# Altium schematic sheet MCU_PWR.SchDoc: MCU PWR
size A4; Date: Not used; ApprovedBy: Not used; CheckedBy: Not used; Author: Not used; CompanyName: STMicroelectronics; DrawnBy: Not used; Engineer: Not used; Organization: Not used; Address1: Not used; Address2: Not used; Address3: Not used; Address4: Not used; DocumentNumber: Not used; Revision: Not used; SheetNumber: 5; SheetTotal: 16
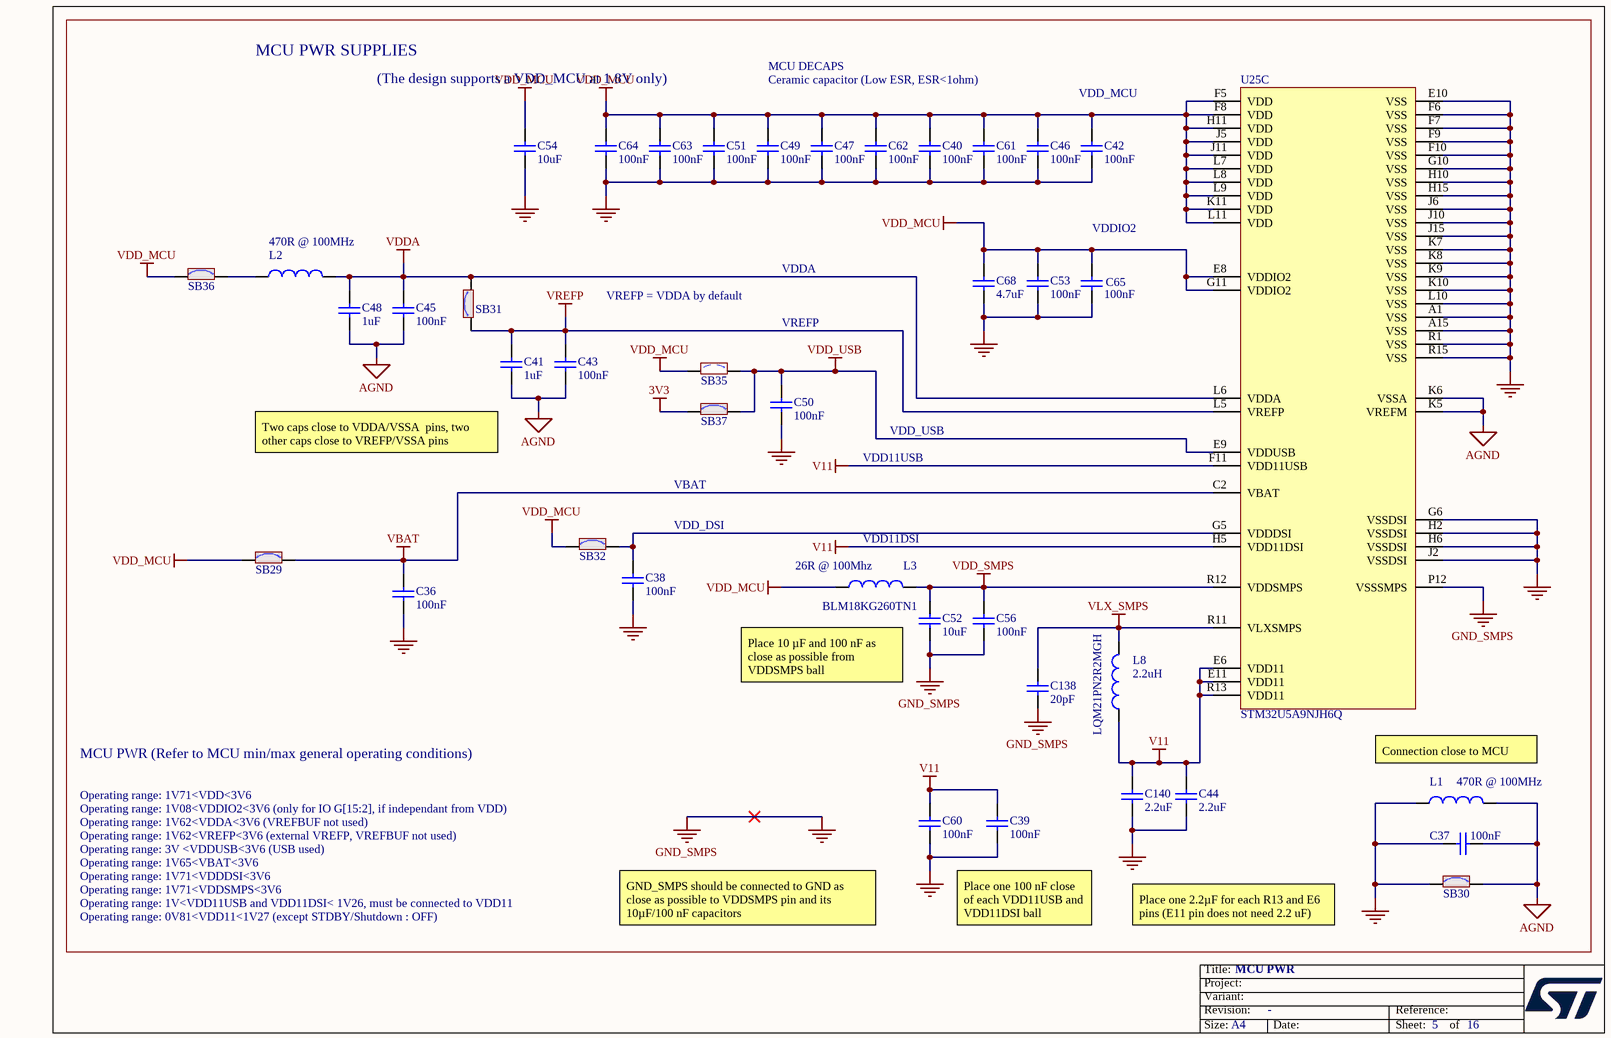
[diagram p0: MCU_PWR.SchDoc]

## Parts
C36  value 100nF  [C0402]  (hidden comment: Capacitor)
C37  value 100nF  [C0402]  (hidden comment: Capacitor)
C38  value 100nF  [C0402]  (hidden comment: Capacitor)
C39  value 100nF  [C0402]  (hidden comment: Capacitor)
C40  value 100nF  [C0402]  (hidden comment: Capacitor)
C41  value 1uF  [C0402]  (hidden comment: Capacitor)
C42  value 100nF  [C0402]  (hidden comment: Capacitor)
C43  value 100nF  [C0402]  (hidden comment: Capacitor)
C44  value 2.2uF  [C0402]  (hidden comment: Capacitor)
C45  value 100nF  [C0402]  (hidden comment: Capacitor)
C46  value 100nF  [C0402]  (hidden comment: Capacitor)
C47  value 100nF  [C0402]  (hidden comment: Capacitor)
C48  value 1uF  [C0402]  (hidden comment: Capacitor)
C49  value 100nF  [C0402]  (hidden comment: Capacitor)
C50  value 100nF  [C0402]  (hidden comment: Capacitor)
C51  value 100nF  [C0402]  (hidden comment: Capacitor)
C52  value 10uF  [C0603_H0P8]  (hidden comment: Capacitor)
C53  value 100nF  [C0402]  (hidden comment: Capacitor)
C54  value 10uF  [C0402]  (hidden comment: Capacitor)
C56  value 100nF  [C0402]  (hidden comment: Capacitor)
C60  value 100nF  [C0402]  (hidden comment: Capacitor)
C61  value 100nF  [C0402]  (hidden comment: Capacitor)
C62  value 100nF  [C0402]  (hidden comment: Capacitor)
C63  value 100nF  [C0402]  (hidden comment: Capacitor)
C64  value 100nF  [C0402]  (hidden comment: Capacitor)
C65  value 100nF  [C0402]  (hidden comment: Capacitor)
C68  value 4.7uF  [C0402]  (hidden comment: Capacitor)
C138  value 20pF  [C0402]  (hidden comment: Capacitor)
C140  value 2.2uF  [C0402]  (hidden comment: Capacitor)
L1  value 470R @ 100MHz  [IND_0402_MURATA_BLM15H_H0P5]  (hidden comment: Inductor)
L2  value 470R @ 100MHz  [IND_0402_MURATA_BLM15H_H0P5]  (hidden comment: Inductor)
L3  value 26R @ 100Mhz  Manufacturer_Part_Number: BLM18KG260TN1  [FIL_0603_H0P65]  (hidden comment: BEAD)
L8  value 2.2uH  Manufacturer_Part_Number: LQM21PN2R2MGH  [L0805_H0P9]  (hidden comment: Inductor)
SB29  SB_ON  [SOLDER-BRIDGE_R0402-0R]  (value not drawn)
SB30  SB_ON  [SOLDER-BRIDGE_R0402-0R]  (value not drawn)
SB31  SB_ON  [SOLDER-BRIDGE_R0402-0R]  (value not drawn)
SB32  SB_ON  [SOLDER-BRIDGE_R0402-0R]  (value not drawn)
SB35  SB_OFF  [SOLDER-BRIDGE_R0402-0R]  (value not drawn)
SB36  SB_ON  [SOLDER-BRIDGE_R0402-0R]  (value not drawn)
SB37  SB_ON  [SOLDER-BRIDGE_R0402-0R]  (value not drawn)
U25  value STM32U5A9NJH6Q  [ICC_TFBGA216_13X13_P080_H1P10_CODE-A0L2]  (hidden comment: STM32U599NJH6Q_BGA216_SMPS)  (part C of 3)

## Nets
3V3: SB37.1
AGND: C37.2 C41.1 C43.1 C45.1 C48.1 L1.2 SB30.2 U25.K5(VREFM) U25.K6(VSSA)
GND: C36.1 C37.1 C38.1 C39.1 C40.1 C42.1 C44.1 C46.1 C47.1 C49.1 C50.1 C51.1 C52.1 C53.1 C54.1 C56.1 C60.1 C61.1 C62.1 C63.1 C64.1 C65.1 C68.1 C138.1 C140.1 L1.1 SB30.1 U25.A1(VSS) U25.A15(VSS) U25.E10(VSS) U25.F6(VSS) U25.F7(VSS) U25.F9(VSS) U25.F10(VSS) U25.G6(VSSDSI) U25.G10(VSS) U25.H2(VSSDSI) U25.H6(VSSDSI) U25.H10(VSS) U25.H15(VSS) U25.J2(VSSDSI) U25.J6(VSS) U25.J10(VSS) U25.J15(VSS) U25.K7(VSS) U25.K8(VSS) U25.K9(VSS) U25.K10(VSS) U25.L10(VSS) U25.P12(VSSSMPS) U25.R1(VSS) U25.R15(VSS)  [also labelled GND_SMPS]
V11: C39.2 C44.2 C60.2 C140.2 L8.1 U25.E6(VDD11) U25.E11(VDD11) U25.F11(VDD11USB) U25.H5(VDD11DSI) U25.R13(VDD11)
VBAT: C36.2 SB29.2 U25.C2(VBAT)
VDD_MCU: C40.2 C42.2 C46.2 C47.2 C49.2 C51.2 C53.2 C54.2 C61.2 C62.2 C63.2 C64.2 C65.2 C68.2 L3.1 SB29.1 SB32.1 SB35.1 SB36.1 U25.E8(VDDIO2) U25.F5(VDD) U25.F8(VDD) U25.G11(VDDIO2) U25.H11(VDD) U25.J5(VDD) U25.J11(VDD) U25.K11(VDD) U25.L7(VDD) U25.L8(VDD) U25.L9(VDD) U25.L11(VDD)
VDD_SMPS: C52.2 C56.2 L3.2 U25.R12(VDDSMPS)
VDD_USB: C50.2 SB35.2 SB37.2 U25.E9(VDDUSB)
VDDA: C45.2 C48.2 L2.2 SB31.2 U25.L6(VDDA)
VLX_SMPS: C138.2 L8.2 U25.R11(VLXSMPS)
VREFP: C41.2 C43.2 SB31.1 U25.L5(VREFP)
NetC38_2: C38.2 SB32.2 U25.G5(VDDDSI)
NetL2_1: L2.1 SB36.2

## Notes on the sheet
- MCU PWR SUPPLIES
- (The design supports a VDD_MCU at 1.8V only)
- MCU DECAPS
- Ceramic capacitor (Low ESR, ESR<1ohm)
- VDD_MCU
- (near C65) VDDIO2
- VREFP = VDDA by default
- VDDA
- VREFP
- (near C41) Two caps close to VDDA/VSSA  pins, two other caps close to VREFP/VSSA pins
- VDD_USB
- VBAT
- VDD11USB
- VDD_DSI
- (near L3) VDD11DSI
- Place 10 µF and 100 nF as close as possible from VDDSMPS ball
- MCU PWR (Refer to MCU min/max general operating conditions)
- Connection close to MCU
- Operating range: 1V71<VDD<3V6
- Operating range: 1V08<VDDIO2<3V6 (only for IO G[15:2], if independant from VDD)
- Operating range: 1V62<VDDA<3V6 (VREFBUF not used)
- Operating range: 3V <VDDUSB<3V6 (USB used)
- Operating range: 1V62<VREFP<3V6 (external VREFP, VREFBUF not used)
- Operating range: 1V65<VBAT<3V6
- Operating range: 1V71<VDDSMPS<3V6
- Operating range: 1V71<VDDDSI<3V6
- Operating range: 1V<VDD11USB and VDD11DSI< 1V26, must be connected to VDD11
- Operating range: 0V81<VDD11<1V27 (except STDBY/Shutdown : OFF)
- GND_SMPS should be connected to GND as close as possible to VDDSMPS pin and its 10µF/100 nF capacitors
- Place one 100 nF close of each VDD11USB and VDD11DSI ball
- Place one 2.2µF for each R13 and E6 pins (E11 pin does not need 2.2 uF)

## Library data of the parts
C36-C40 C42 C43 C45-C47 C49-C51 C53 C56 C60-C65 = MCD-00006: Capacitor, MLCC, 100nF, 16V, X7R, +/-10%, 0402, T=0.5mm; Manufacturer_Part_Number: CC0402KRX7R7BB104; Manufacturer: YAGEO; Part_Preference: Recommended; Order_Code_RS: 616-9701; Component_Country_Of_Origin: China
C41 C48 = MCD-01722: Capacitor, MLCC, 1uF, 10V, X5R, +/-10%, 0402, T=0.5mm; Manufacturer_Part_Number: CC0402KRX5R6BB105; Manufacturer: YAGEO; Part_Preference: Recommended; Component_Country_Of_Origin: China
C44 C140 = MCD-02606: Capacitor, MLCC, 2.2uF, 6.3V, X5R, +/-10%, 0402, T=0.5mm; Part_Preference: Recommended; Manufacturer: YAGEO; Manufacturer_Part_Number: CC0402KRX5R5BB225; Order_Code_RS: 1992205
C52 = MCD-02605: Capacitor, MLCC, 10uF, 10V, X5R, +/-10%, 0603, T=0.8mm; Part_Preference: Recommended; Manufacturer: YAGEO; Manufacturer_Part_Number: CC0603KRX5R6BB106; Order_Code_RS: 2006536
C54 = MCD-01716: Capacitor, MLCC, 10uF, 6V3, X5R, +/-20%, 0402, T=0.5mm; Part_Preference: Recommended; Manufacturer: YAGEO; Manufacturer_Part_Number: CC0402MRX5R5BB106; Component_Country_Of_Origin: China
C68 = MCD-02608: Capacitor, MLCC, 4.7uF, 6.3V, X5R, +/-10%, 0402, T=0.5mm; Part_Preference: Recommended; Manufacturer: YAGEO; Manufacturer_Part_Number: CC0402KRX5R5BB475
C138 = MCD-00016: Capacitor, MLCC, 20pF, 50V, NPO, +/- 5%, 0402, T=0.5mm; Manufacturer: YAGEO; Manufacturer_Part_Number: CC0402JRNPO9BN200; Part_Preference: Recommended; Component_Country_Of_Origin: China
L1 L2 = MCD-01986: Ferrite bead, 470R @ 100MHz, +/-25%, 200mA, 0R6, 0402, T=0.55mm; Manufacturer_Part_Number: BLM15BD471SN1D; Manufacturer: MURATA; Part_Preference: Recommended; Order_Code_RS: 166-9836; Component_Country_Of_Origin: Japan
L3 = MCD-00305: Ferrite bead, 26R @ 100Mhz, +/-25%, 6000mA, 0R007, 0603, T=0.75mm; Part_Type: Inductor; Manufacturer: MURATA; Part_Preference: Recommended; Order_Code_RS: 747-4723; Component_Country_Of_Origin: Japan
L8 = MCD-01060: Inductor, 2.2uH, +/-20%, 0.7A, 0R156, 0805, T=0.9mm; Manufacturer: MURATA; Part_Preference: Recommended; Order_Code_RS: 166-9883; Component_Country_Of_Origin: Japan
SB29-SB32 SB36 SB37 = MCD-01618: Solder Bridge 0402 ON; Part_Type: Misc; Manufacturer_Part_Number: RC0402JR-070RL; Manufacturer: YAGEO; Part_Preference: Recommended; Order_Code_RS: 618-5804; Component_Country_Of_Origin: China
SB35 = MCD-02162: Solder Bridge 0402 OFF; Part_Type: Misc; Manufacturer_Part_Number: RC0402JR-070RL; Manufacturer: YAGEO; Part_Preference: Recommended; Order_Code_RS: 618-5804; Component_Country_Of_Origin: China
U25 = MCD-03270: MCU, ARM Cortex-M33, 4MB Flash, 2.5MB RAM, With Crypto; Part_Type: IC; Part_Preference: Recommended; Manufacturer: STMICROELECTRONICS; Component_Country_Of_Origin: Unknown; ShowFields: YES; ID: 5386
